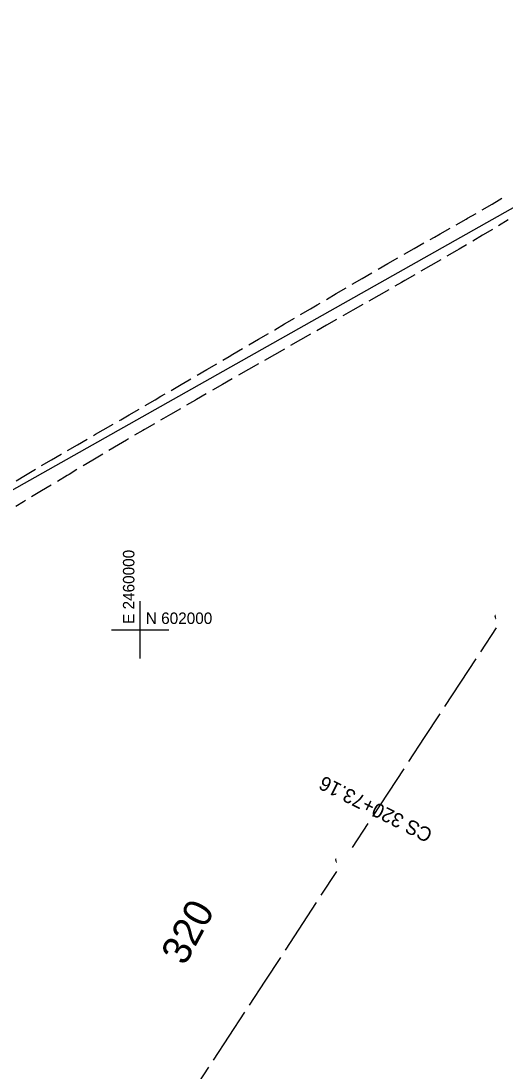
# Model space of a CAD drawing. Extents: x 2443269 to 2494951, y 591171 to 622130.
# Drawn here: x 2459958.4 to 2460127.4, y 601846 to 602212.4 of the extents above; entities that cross this region are included whole.
import ezdxf

# ---------------------------------------------------------------- set-up
doc = ezdxf.new("R2010")
doc.units = 0
for name, color, linetype in [('SURVEY - CENTERLINE - Preliminary Curve Text', 7, 'Continuous'), ('SURVEY - CENTERLINE - Preliminary Text', 7, 'Continuous'), ('SURVEY - CONTROL - Grid', 7, 'Continuous'), ('SURVEY - CONTROL - Grid Text', 7, 'Continuous'), ('SURVEY - DRAINAGE - Area Shapes', 7, 'Continuous'), ('SURVEY - PROPERTY - ROW Lines', 7, 'Continuous'), ('SURVEY - TRANSPORTATION - Features', 7, 'Continuous'), ('SURVEY - UTILITIES - Electric (Overhead) with Text', 7, 'Continuous')]:
    doc.layers.add(name, color=color, linetype=linetype)

msp = doc.modelspace()

# ---------------------------------------------------------------- linework, layer by layer
at = {"layer": 'SURVEY - CONTROL - Grid'}
for p, q in [((2460000, 601990), (2460000, 602010)), ((2459990, 602000), (2460010, 602000))]:
    msp.add_line(p, q, dxfattribs=at)
at = {"layer": 'SURVEY - DRAINAGE - Area Shapes'}
msp.add_lwpolyline([(2460353.962, 601945.026), (2460249.104, 601770.977), (2460013.973, 601448.937), (2459806.928, 601226.151), (2459621.896, 601062.242), (2459499.028, 600967.526), (2459400.545, 601059.837), (2459309.68, 601130.037), (2459144.081, 601205.667), (2459060.551, 601360.442), (2459079.372, 601494.233), (2459186.712, 601618.749), (2459933.066, 602036.23), (2460201.434, 602187.308), (2460285.186, 602311.676), (2460445.562, 602442.421), (2460611.845, 602514.091), (2460491.296, 602232.712)], close=True, dxfattribs=at)
at = {"layer": 'SURVEY - PROPERTY - ROW Lines'}
msp.add_arc((2457760.017, 603350.452), 2825, 304.10395, 336.530581, dxfattribs=at)
at = {"layer": 'SURVEY - TRANSPORTATION - Features'}
for p, q in [((2460125.457, 602149.987), (2460126.381, 602150.551)), ((2460119.495, 602146.532), (2460122.944, 602148.531)), ((2460122.944, 602148.531), (2460125.457, 602149.987)), ((2460110.416, 602141.326), (2460113.886, 602143.289)), ((2460113.886, 602143.289), (2460114.394, 602143.576)), ((2460114.394, 602143.576), (2460117.339, 602145.283)), ((2460104.777, 602138.136), (2460108.247, 602140.099)), ((2460123.036, 602139.71), (2460119.61, 602137.664)), ((2460128.603, 602143.035), (2460125.177, 602140.989)), ((2460101.306, 602136.175), (2460102.819, 602137.028)), ((2460102.819, 602137.028), (2460104.777, 602138.136)), ((2460119.61, 602137.664), (2460116.184, 602135.618)), ((2460092.189, 602131.037), (2460095.662, 602132.994)), ((2460095.662, 602132.994), (2460099.135, 602134.952)), ((2460110.611, 602132.305), (2460107.156, 602130.309)), ((2460111.421, 602132.773), (2460110.611, 602132.305)), ((2460114.043, 602134.339), (2460111.421, 602132.773)), ((2460086.567, 602127.817), (2460090.026, 602129.799)), ((2460104.996, 602129.061), (2460101.541, 602127.065)), ((2460083.107, 602125.835), (2460086.567, 602127.817)), ((2460101.541, 602127.065), (2460098.086, 602125.069)), ((2460074.066, 602120.565), (2460077.509, 602122.574)), ((2460077.509, 602122.574), (2460080.953, 602124.583)), ((2460092.471, 602121.826), (2460091.254, 602121.122)), ((2460095.926, 602123.822), (2460092.471, 602121.826)), ((2460068.478, 602117.286), (2460071.916, 602119.305)), ((2460086.838, 602118.615), (2460083.368, 602116.644)), ((2460091.254, 602121.122), (2460089.006, 602119.846)), ((2460061.835, 602113.383), (2460062.892, 602114.004)), ((2460065.041, 602115.266), (2460068.478, 602117.286)), ((2460083.368, 602116.644), (2460079.898, 602114.674)), ((2460056.015, 602109.968), (2460059.454, 602111.986)), ((2460059.454, 602111.986), (2460061.835, 602113.383)), ((2460074.26, 602111.472), (2460071.08, 602109.666)), ((2460077.73, 602113.442), (2460074.26, 602111.472)), ((2460047.005, 602104.682), (2460050.427, 602106.69)), ((2460050.427, 602106.69), (2460053.866, 602108.707)), ((2460068.619, 602108.273), (2460065.147, 602106.308)), ((2460071.08, 602109.666), (2460070.79, 602109.501)), ((2460041.399, 602101.396), (2460044.839, 602103.412)), ((2460046.988, 602104.672), (2460047.005, 602104.682)), ((2460059.504, 602103.114), (2460056.031, 602101.148)), ((2460065.147, 602106.308), (2460061.674, 602104.342)), ((2460037.959, 602099.38), (2460041.399, 602101.396)), ((2460056.031, 602101.148), (2460052.559, 602099.183)), ((2460031.064, 602095.338), (2460032.37, 602096.104)), ((2460032.37, 602096.104), (2460035.81, 602098.12)), ((2460046.925, 602095.972), (2460043.46, 602093.994)), ((2460050.391, 602097.949), (2460046.925, 602095.972)), ((2460023.337, 602090.818), (2460026.779, 602092.831)), ((2460028.929, 602094.09), (2460031.064, 602095.338)), ((2460041.294, 602092.758), (2460037.828, 602090.78)), ((2460019.896, 602088.805), (2460023.337, 602090.818)), ((2460037.828, 602090.78), (2460034.362, 602088.803)), ((2460010.859, 602083.527), (2460014.302, 602085.536)), ((2460014.302, 602085.536), (2460017.1, 602087.169)), ((2460017.1, 602087.169), (2460017.746, 602087.546)), ((2460028.741, 602085.57), (2460025.283, 602083.58)), ((2460032.2, 602087.56), (2460028.741, 602085.57)), ((2460005.26, 602080.267), (2460007.284, 602081.441)), ((2460007.284, 602081.441), (2460008.707, 602082.271)), ((2460023.121, 602082.336), (2460019.662, 602080.347)), ((2460001.812, 602078.266), (2460005.26, 602080.267)), ((2460019.328, 602080.155), (2460016.207, 602078.351)), ((2460019.662, 602080.347), (2460019.328, 602080.155)), ((2459993.206, 602073.291), (2459996.204, 602075.022)), ((2459996.204, 602075.022), (2459999.656, 602077.016)), ((2460008.173, 602073.708), (2460007.139, 602073.108)), ((2460010.593, 602075.106), (2460008.173, 602073.708)), ((2460014.048, 602077.103), (2460010.593, 602075.106)), ((2459987.14, 602069.789), (2459990.593, 602071.782)), ((2459992.751, 602073.028), (2459993.206, 602073.291)), ((2460001.529, 602069.857), (2460001.001, 602069.551)), ((2460004.981, 602071.858), (2460001.529, 602069.857)), ((2459978.088, 602064.538), (2459981.535, 602066.541)), ((2459983.689, 602067.794), (2459984.364, 602068.186)), ((2459984.364, 602068.186), (2459987.14, 602069.789)), ((2459995.933, 602066.58), (2459995.198, 602066.149)), ((2460001.001, 602069.551), (2459998.085, 602067.841)), ((2459974.641, 602062.534), (2459978.088, 602064.538)), ((2459992.5, 602064.546), (2459989.07, 602062.508)), ((2459995.198, 602066.149), (2459992.5, 602064.546)), ((2459965.61, 602057.246), (2459969.048, 602059.264)), ((2459969.048, 602059.264), (2459972.471, 602061.273)), ((2459972.471, 602061.273), (2459972.486, 602061.282)), ((2459983.5, 602059.187), (2459980.075, 602057.141)), ((2459986.926, 602061.233), (2459983.5, 602059.187)), ((2459960.023, 602053.966), (2459963.461, 602055.984)), ((2459977.934, 602055.863), (2459975.171, 602054.213)), ((2459956.654, 602051.989), (2459960.023, 602053.966)), ((2459974.508, 602053.816), (2459971.086, 602051.764)), ((2459975.171, 602054.213), (2459974.508, 602053.816)), ((2459965.524, 602048.431), (2459962.101, 602046.38)), ((2459968.947, 602050.482), (2459965.524, 602048.431)), ((2459959.253, 602044.672), (2459956.543, 602043.04)), ((2459959.962, 602045.098), (2459959.253, 602044.672))]:
    msp.add_line(p, q, dxfattribs=at)
at = {"layer": 'SURVEY - UTILITIES - Electric (Overhead) with Text'}
for p, q in [((2460118.971, 601992.319), (2460124.43, 602000.652)), ((2460106.416, 601973.153), (2460117.334, 601989.819)), ((2460099.319, 601962.32), (2460104.778, 601970.653)), ((2460093.86, 601953.986), (2460099.319, 601962.32)), ((2460081.304, 601934.82), (2460092.222, 601951.486)), ((2460074.208, 601923.987), (2460079.667, 601932.32)), ((2460063.29, 601907.32), (2460068.749, 601915.654)), ((2460050.734, 601888.154), (2460061.652, 601904.82)), ((2460043.637, 601877.321), (2460049.096, 601885.654)), ((2460038.178, 601868.988), (2460043.637, 601877.321)), ((2460025.623, 601849.821), (2460036.541, 601866.488)), ((2460018.526, 601838.988), (2460023.985, 601847.321))]:
    msp.add_line(p, q, dxfattribs=at)

# ---------------------------------------------------------------- texts
at = {"layer": 'SURVEY - CENTERLINE - Preliminary Curve Text'}
msp.add_text('CS 320+73.16', height=5, rotation=153.41047, dxfattribs=at).set_placement((2460102.566, 601929.946))
at = {"layer": 'SURVEY - CENTERLINE - Preliminary Text'}
msp.add_text('320', height=10, rotation=61.58145, dxfattribs=at).set_placement((2460015.627, 601882.44))
at = {"layer": 'SURVEY - CONTROL - Grid Text'}
msp.add_text('E 2460000', height=4, rotation=90, dxfattribs=at).set_placement((2459998, 602002))
msp.add_text('N 602000', height=4, dxfattribs=at).set_placement((2460002, 602002))
at = {"layer": 'SURVEY - UTILITIES - Electric (Overhead) with Text'}
for p in [(2460127.653, 602001.009), (2460071.971, 601916.011)]:
    msp.add_text('´', height=5, rotation=56.77174, dxfattribs=at).set_placement(p)

doc.saveas('drawing.dxf')
